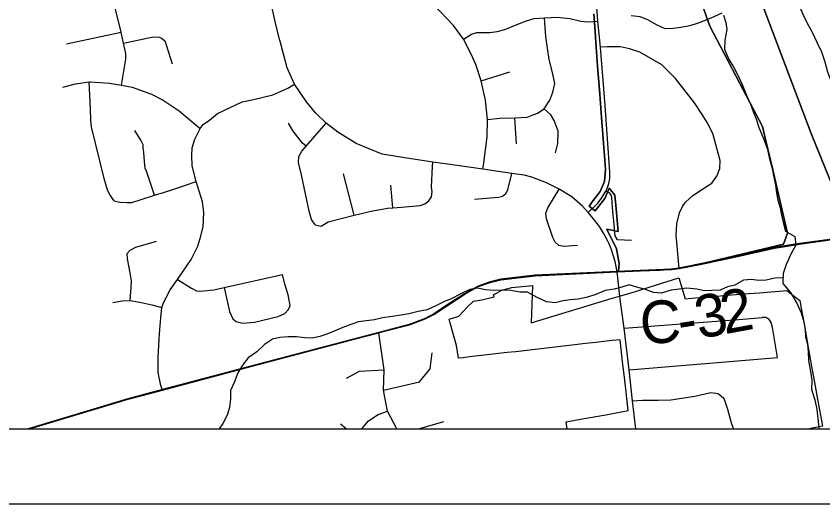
# Model space of a CAD drawing. Extents: x 0 to 34, y 0 to 22.
# Drawn here: x 13.284 to 14.359, y 3.284 to 3.934 of the extents above; entities that cross this region are included whole.
import ezdxf

# ---------------------------------------------------------------- set-up
doc = ezdxf.new("R2010")
doc.units = 0
for name, color, linetype in [('GM_X_City_Street', 7, 'Continuous'), ('GM_X_Corporation', 7, 'Continuous'), ('GM_X_County_Road', 7, 'Continuous'), ('GM_X_County_Road_Text', 7, 'Continuous'), ('GM_X_Major_River', 7, 'Continuous'), ('GM_X_Minor_River', 7, 'Continuous'), ('GM_X_Township_Road', 7, 'Continuous'), ('SH_Data', 7, 'Continuous')]:
    doc.layers.add(name, color=color, linetype=linetype)

msp = doc.modelspace()

# ---------------------------------------------------------------- linework, layer by layer
at = {"layer": 'GM_X_City_Street'}
for p, q in [((13.3512, 3.8973), (13.4237, 3.9129)), ((13.9039, 3.8481), (13.9422, 3.8599)), ((13.9508, 3.7642), (13.9488, 3.7987)), ((13.7344, 3.669), (13.7204, 3.7243)), ((13.786, 3.6789), (13.7836, 3.7088)), ((14.0819, 3.6463), (14.0801, 3.6657)), ((13.7237, 3.3841), (13.7163, 3.3904))]:
    msp.add_line(p, q, dxfattribs=at)
for points in [[(13.635, 3.9032), (13.629, 3.9271), (13.6186, 3.9755), (13.5999, 4.0534), (13.5519, 4.2807)], [(13.9123, 3.7967), (13.9094, 3.8222), (13.9039, 3.8481), (13.8968, 3.8698), (13.8907, 3.8836), (13.8802, 3.9037), (13.8671, 3.9217), (13.8411, 3.9489), (13.8248, 3.9626), (13.8, 3.986), (13.77, 4.011), (13.7495, 4.0206), (13.7309, 4.0238), (13.7079, 4.0206), (13.6893, 4.0135), (13.6778, 4.0065), (13.6669, 3.9937), (13.6571, 3.9868)], [(13.4241, 3.8422), (13.4288, 3.8688), (13.4301, 3.8768), (13.43, 3.8844), (13.4271, 3.8981), (13.4263, 3.9025), (13.4237, 3.9129), (13.4146, 3.9508), (13.4111, 3.9655), (13.4063, 3.9854), (13.4016, 4.0049)], [(13.8802, 3.9037), (13.8911, 3.9101), (13.8981, 3.9124), (13.907, 3.9127), (13.9154, 3.9127), (13.9253, 3.914), (13.9352, 3.9165), (13.955, 3.9245), (13.9643, 3.9281), (13.9746, 3.931), (13.9884, 3.9322), (13.9973, 3.9326)], [(13.9123, 3.7967), (13.9288, 3.7983), (13.9488, 3.7987), (13.9653, 3.7995), (13.9718, 3.8022), (13.9788, 3.805), (13.9878, 3.8108), (13.9955, 3.8221), (13.9994, 3.833), (14.0019, 3.8445), (13.9991, 3.8592), (13.9945, 3.8766), (13.9898, 3.9067), (13.9884, 3.9322)], [(13.9973, 3.9326), (14.0053, 3.9329), (14.0222, 3.9313), (14.0369, 3.9278), (14.0465, 3.9268), (14.0594, 3.9274)], [(13.4271, 3.8981), (13.4664, 3.9065), (13.474, 3.9064), (13.4772, 3.9054), (13.4821, 3.9016), (13.484, 3.8959), (13.4917, 3.8708)], [(14.0465, 3.6724), (14.0391, 3.6811), (14.0245, 3.6936), (14.0079, 3.7036), (13.991, 3.7122), (13.9713, 3.7197), (13.9613, 3.7222), (13.9447, 3.7247), (13.9061, 3.7305), (13.8654, 3.7362), (13.8394, 3.7398), (13.8019, 3.7452), (13.772, 3.7503), (13.7372, 3.7645), (13.7129, 3.7795), (13.6972, 3.7917), (13.6831, 3.8052), (13.671, 3.82), (13.655, 3.8436), (13.645, 3.8656), (13.6353, 3.9021), (13.635, 3.9032)], [(14.1677, 3.5979), (14.1637, 3.6421), (14.1645, 3.6575), (14.1681, 3.672), (14.1724, 3.6807), (14.1764, 3.6863), (14.1861, 3.6954), (14.2016, 3.7053), (14.2112, 3.7118), (14.2182, 3.721), (14.222, 3.7311), (14.2226, 3.7418), (14.2125, 3.778), (14.2051, 3.7924), (14.1995, 3.802), (14.1882, 3.8187), (14.163, 3.8512), (14.1447, 3.8692), (14.1154, 3.8864), (14.1016, 3.8909), (14.0894, 3.8932), (14.0717, 3.8936), (14.0627, 3.8929)], [(13.346, 3.8397), (13.363, 3.844), (13.3811, 3.8466), (13.3824, 3.8468), (13.4083, 3.8451), (13.4241, 3.8422), (13.4386, 3.8396), (13.4642, 3.8302), (13.4799, 3.8222), (13.5012, 3.8082), (13.5294, 3.7847)], [(13.4146, 3.6881), (13.4091, 3.6957), (13.4058, 3.7023), (13.4012, 3.718), (13.3843, 3.7867), (13.3835, 3.7953), (13.3832, 3.8106), (13.3811, 3.8466)], [(13.4792, 3.4358), (13.4769, 3.4417), (13.473, 3.4593), (13.473, 3.4794), (13.4751, 3.5113), (13.4766, 3.5323), (13.4783, 3.5458), (13.4801, 3.5521), (13.489, 3.5693), (13.499, 3.5834), (13.5174, 3.6098), (13.5259, 3.6275), (13.5297, 3.6398), (13.5331, 3.6536), (13.5339, 3.6725), (13.5322, 3.6869), (13.524, 3.7138), (13.5186, 3.7347), (13.518, 3.7487), (13.5187, 3.7588), (13.522, 3.7701), (13.5294, 3.7847), (13.5334, 3.7899), (13.5416, 3.7956), (13.5523, 3.8046), (13.5853, 3.8202), (13.6005, 3.823), (13.6259, 3.8294), (13.6462, 3.8382), (13.655, 3.8436)], [(14.0031, 3.7521), (14.0062, 3.7644), (14.0064, 3.7811), (14.0013, 3.7952), (13.9966, 3.8026), (13.9878, 3.8108)], [(13.9061, 3.7305), (13.9072, 3.7389), (13.9119, 3.7736), (13.9123, 3.7967)], [(13.6704, 3.761), (13.6654, 3.765), (13.6531, 3.7808), (13.6469, 3.7917)], [(13.6827, 3.656), (13.6777, 3.6633), (13.6744, 3.6744), (13.6642, 3.7227), (13.6605, 3.7392), (13.6609, 3.7471), (13.6646, 3.7541), (13.6704, 3.761), (13.6972, 3.7917)], [(13.4684, 3.6955), (13.4577, 3.7276), (13.4559, 3.7318), (13.4551, 3.7403), (13.454, 3.7529), (13.4534, 3.7583), (13.4531, 3.7627), (13.4503, 3.7691), (13.442, 3.7819)], [(13.6827, 3.656), (13.6905, 3.6542), (13.6998, 3.66), (13.7344, 3.669), (13.7571, 3.6745), (13.7789, 3.6782), (13.786, 3.6789), (13.7977, 3.6797), (13.8226, 3.6819), (13.8287, 3.684), (13.8339, 3.6879), (13.8375, 3.6934), (13.8384, 3.6999), (13.8378, 3.7063), (13.8389, 3.7339), (13.8394, 3.7398)], [(13.8949, 3.6904), (13.9268, 3.6929), (13.9323, 3.6943), (13.9367, 3.6979), (13.9393, 3.7029), (13.9447, 3.7247)], [(13.4146, 3.6881), (13.4222, 3.6863), (13.4314, 3.6858), (13.4381, 3.686), (13.4491, 3.6893), (13.4684, 3.6955), (13.4801, 3.6993), (13.4952, 3.704), (13.524, 3.7138)], [(14.0324, 3.6285), (14.014, 3.627), (14.0074, 3.6287), (14.0023, 3.6332), (13.9995, 3.6394), (13.9907, 3.6642), (13.99, 3.6718), (13.9925, 3.6789), (14.0079, 3.7036)], [(14.0801, 3.6657), (14.0798, 3.6686), (14.0783, 3.6854), (14.078, 3.693), (14.0771, 3.6958), (14.0753, 3.6981), (14.07, 3.7011)], [(14.0739, 3.6316), (14.0732, 3.6335), (14.0671, 3.645), (14.0617, 3.6539), (14.0537, 3.6643), (14.0465, 3.6724)], [(14.1044, 3.635), (14.0855, 3.6363), (14.0824, 3.6415), (14.0819, 3.6463)], [(13.436, 3.5552), (13.4372, 3.5724), (13.4375, 3.5814), (13.4357, 3.592), (13.4321, 3.6106), (13.4318, 3.618), (13.4357, 3.6224), (13.4434, 3.6263), (13.4709, 3.6345)], [(14.0852, 3.5936), (14.0825, 3.6073), (14.0769, 3.6241), (14.0739, 3.6316)], [(13.499, 3.5834), (13.5177, 3.5718), (13.5245, 3.5683), (13.5289, 3.5675), (13.534, 3.568), (13.5473, 3.5694), (13.5611, 3.5725), (13.639, 3.5899)], [(13.5611, 3.5725), (13.5681, 3.5407), (13.5727, 3.5308), (13.5774, 3.5273), (13.5859, 3.5251), (13.6018, 3.5262), (13.6334, 3.5341), (13.642, 3.5381), (13.6471, 3.5432), (13.6493, 3.5485), (13.6463, 3.5628), (13.6419, 3.5771), (13.639, 3.5899)], [(13.4129, 3.5524), (13.4254, 3.5546), (13.436, 3.5552), (13.4486, 3.5528), (13.4647, 3.5496), (13.4783, 3.5458)], [(13.7916, 3.3841), (13.7789, 3.4077), (13.7737, 3.4355), (13.7743, 3.4629), (13.7674, 3.5122)], [(13.7737, 3.4355), (13.8214, 3.4467), (13.836, 3.4643), (13.8385, 3.4853)], [(13.7244, 3.4518), (13.7418, 3.4609), (13.7743, 3.4629)], [(13.7448, 3.3841), (13.7537, 3.3949), (13.7663, 3.4031), (13.7789, 3.4077)], [(13.8202, 3.3841), (13.8219, 3.3848), (13.854, 3.3938)]]:
    msp.add_lwpolyline(points, dxfattribs=at)
at = {"layer": 'GM_X_Corporation'}
for points in [[(12.7646, 8.6719), (12.7646, 3.3841), (19.5646, 3.3841), (19.5646, 8.318)], [(12.7646, 8.6719), (12.7646, 3.3841), (13.2998, 3.3841), (13.4327, 3.4241), (13.4789, 3.4364), (13.6099, 3.4712), (13.7672, 3.5127), (13.8079, 3.5231), (13.829, 3.5313), (13.8415, 3.5378), (13.8572, 3.5484), (13.8817, 3.5643), (13.8998, 3.5742), (13.9157, 3.5799), (13.9299, 3.5835), (13.9754, 3.5888), (14.085, 3.5941), (14.1571, 3.5969), (14.1675, 3.5985), (14.2018, 3.6051), (14.2415, 3.6134), (14.2946, 3.6257), (14.328, 3.631), (14.375, 3.6376)], [(14.4, 3.6389), (14.3439, 3.7779), (14.2585, 4.0037), (14.2228, 4.1239), (14.1834, 4.3256), (14.1653, 4.4698)], [(14.1653, 4.4698), (14.1834, 4.3256), (14.2228, 4.1239), (14.2585, 4.0037), (14.3439, 3.7779), (14.4, 3.6389)], [(14.0541, 3.9374), (14.0552, 3.9202), (14.0572, 3.893), (14.0595, 3.8618), (14.0603, 3.852), (14.0619, 3.8304), (14.0643, 3.799), (14.0665, 3.7706), (14.0687, 3.7422), (14.0697, 3.7297), (14.0683, 3.7145), (14.067, 3.7108), (14.0626, 3.7004), (14.0533, 3.6884), (14.048, 3.681), (14.0556, 3.6748), (14.0686, 3.691), (14.0745, 3.7049), (14.0818, 3.6958), (14.0836, 3.6776), (14.0866, 3.6474), (14.0715, 3.6501), (14.0843, 3.6241), (14.0877, 3.6045), (14.0869, 3.5941), (14.1423, 3.5958), (14.1573, 3.5969), (14.1675, 3.5985), (14.2018, 3.6051), (14.3069, 3.6302), (14.3122, 3.645), (14.3015, 3.6909), (14.2925, 3.7296), (14.2835, 3.7682), (14.279, 3.7873), (14.2701, 3.8041), (14.2486, 3.8445), (14.2276, 3.8847), (14.2086, 3.9211), (14.1912, 3.9702)], [(14.1912, 3.9702), (14.2086, 3.9211), (14.2276, 3.8847), (14.2486, 3.8445), (14.2701, 3.8041), (14.279, 3.7873), (14.2835, 3.7682), (14.2925, 3.7296), (14.3015, 3.6909), (14.3122, 3.645), (14.3069, 3.6302), (14.2026, 3.6053), (14.1675, 3.5985), (14.1573, 3.5969), (14.1423, 3.5958), (14.0869, 3.5941), (14.0877, 3.6047), (14.0843, 3.6241), (14.0715, 3.6501), (14.0866, 3.6474), (14.0836, 3.6776), (14.0818, 3.6958), (14.0745, 3.7049), (14.0686, 3.691), (14.0556, 3.6748), (14.048, 3.681), (14.0533, 3.6884), (14.0626, 3.7004), (14.067, 3.7108), (14.0683, 3.7145), (14.0697, 3.7297), (14.0687, 3.7422), (14.0665, 3.7706), (14.0643, 3.799), (14.0619, 3.8304), (14.0595, 3.8618), (14.0572, 3.893), (14.0552, 3.9202), (14.0541, 3.9374)], [(14.375, 3.6376), (14.328, 3.631), (14.2946, 3.6257), (14.2415, 3.6134), (14.2018, 3.6051), (14.1675, 3.5985), (14.1571, 3.5969), (14.085, 3.5941), (13.9754, 3.5888), (13.9299, 3.5835), (13.9157, 3.5799), (13.8998, 3.5742), (13.8817, 3.5643), (13.8572, 3.5484), (13.8415, 3.5378), (13.829, 3.5313), (13.8079, 3.5231), (13.7672, 3.5127), (13.6099, 3.4712), (13.4789, 3.4364), (13.4327, 3.4241), (13.2998, 3.3841), (14.4192, 3.3841)], [(13.0687, 3.3841), (14.0184, 3.3841), (14.0171, 3.3935), (14.0413, 3.3979), (14.0698, 3.403), (14.1, 3.4085), (14.0995, 3.4127), (14.0962, 3.4408), (14.0947, 3.4531), (14.0927, 3.47), (14.0889, 3.5026), (14.0784, 3.5019), (14.0675, 3.5006), (14.0567, 3.4994), (14.0427, 3.4978), (14.0287, 3.4962), (14.0174, 3.4949), (14.0061, 3.4936), (13.9948, 3.4923), (13.9835, 3.491), (13.9722, 3.4896), (13.961, 3.4883), (13.9497, 3.487), (13.9384, 3.4857), (13.9271, 3.4844), (13.9158, 3.4831), (13.9004, 3.4814), (13.8883, 3.48), (13.8796, 3.479), (13.8735, 3.4782), (13.8708, 3.4953), (13.8622, 3.5268), (13.8612, 3.5305), (13.874, 3.5343), (13.8857, 3.547), (13.8936, 3.5543), (13.9046, 3.556), (13.921, 3.5599), (13.9203, 3.5629), (13.9312, 3.569), (13.9449, 3.5724), (13.9722, 3.575), (13.9706, 3.5256), (14.0772, 3.5581), (14.1036, 3.5656), (14.1363, 3.5758), (14.1673, 3.5855), (14.1756, 3.5575), (14.1897, 3.5586), (14.2039, 3.5598), (14.218, 3.5609), (14.2321, 3.5622), (14.2606, 3.5644), (14.2747, 3.5654), (14.3113, 3.5684), (14.3285, 3.5552), (14.3304, 3.5448), (14.3338, 3.5262), (14.336, 3.5136), (14.3403, 3.4898), (14.3444, 3.4674), (14.3465, 3.4556), (14.3487, 3.4437), (14.3527, 3.4211), (14.3561, 3.4023), (14.3588, 3.3877), (14.3412, 3.3841), (14.5215, 3.3841)]]:
    msp.add_lwpolyline(points, dxfattribs=at)
at = {"layer": 'GM_X_County_Road'}
msp.add_line((14.0887, 3.561), (14.0852, 3.5936), dxfattribs=at)
for points in [[(14.07, 3.7011), (14.0716, 3.7047), (14.0739, 3.7113), (14.0752, 3.7177), (14.0752, 3.7265), (14.0693, 3.8153), (14.0627, 3.8929), (14.0594, 3.9274), (14.052, 4.0359), (14.049, 4.0744), (14.0366, 4.2397), (14.0264, 4.3631), (14.0059, 4.4877), (13.9877, 4.5872), (13.9741, 4.6416), (13.9708, 4.6584), (13.9579, 4.7101), (13.9565, 4.7165), (13.9561, 4.7239), (13.9561, 4.7298), (13.9561, 4.7351)], [(14.0465, 3.6724), (14.0593, 3.6852), (14.0644, 3.6915), (14.07, 3.7011)], [(14.0739, 3.6316), (14.0732, 3.6335), (14.0671, 3.645), (14.0617, 3.6539), (14.0537, 3.6643), (14.0465, 3.6724)], [(14.309, 3.6274), (14.3282, 3.6304), (14.3752, 3.637), (14.4003, 3.6384)], [(14.0852, 3.5936), (14.0825, 3.6073), (14.0769, 3.6241), (14.0739, 3.6316)], [(14.1979, 3.6038), (14.202, 3.6046), (14.2417, 3.6129), (14.2948, 3.6251), (14.309, 3.6274)], [(14.0852, 3.5936), (14.1574, 3.5964), (14.1677, 3.5979), (14.1979, 3.6038)], [(13.7769, 3.5146), (13.8082, 3.5226), (13.8292, 3.5307), (13.8417, 3.5372), (13.8574, 3.5478), (13.8819, 3.5637), (13.9, 3.5737), (13.9159, 3.5794), (13.9301, 3.5829), (13.9756, 3.5882), (14.0852, 3.5936)], [(14.1101, 3.3841), (14.1057, 3.4215), (14.1009, 3.4627), (14.0946, 3.5183), (14.0895, 3.5534), (14.0887, 3.561)], [(13.3018, 3.3841), (13.433, 3.4236), (13.4792, 3.4358), (13.6101, 3.4707), (13.7482, 3.5071)], [(13.7482, 3.5071), (13.7674, 3.5122), (13.7769, 3.5146)]]:
    msp.add_lwpolyline(points, dxfattribs=at)
at = {"layer": 'GM_X_Major_River'}
msp.add_line((14.354, 3.3857), (14.3543, 3.3841), dxfattribs=at)
for points in [[(14.375, 3.8387), (14.3695, 3.8502), (14.3659, 3.8598), (14.3624, 3.8731), (14.3581, 3.8861), (14.3519, 3.8991), (14.3457, 3.9126), (14.3388, 3.9245), (14.3333, 3.9367), (14.3268, 3.9513), (14.3207, 3.9658), (14.3156, 3.9785), (14.3113, 3.9911), (14.3085, 4.0006), (14.3046, 4.0128), (14.3018, 4.0258), (14.299, 4.0365), (14.2951, 4.0495), (14.2908, 4.0629)], [(14.2268, 3.9358), (14.23, 3.9258), (14.2313, 3.9163), (14.2288, 3.9023), (14.2282, 3.8905), (14.2336, 3.8772), (14.2402, 3.8668), (14.2457, 3.8564), (14.2518, 3.843), (14.2573, 3.83), (14.2627, 3.817), (14.2663, 3.8074), (14.271, 3.7959), (14.2742, 3.786), (14.2803, 3.7714), (14.285, 3.7581), (14.2881, 3.7439), (14.2917, 3.731), (14.2941, 3.7195), (14.2961, 3.7089), (14.2974, 3.6986), (14.2995, 3.689), (14.3024, 3.6787), (14.3041, 3.6692), (14.3065, 3.6597), (14.3097, 3.6478), (14.322, 3.6404), (14.3233, 3.629), (14.317, 3.6177), (14.3103, 3.6034), (14.3063, 3.5913), (14.306, 3.5777), (14.3164, 3.5657), (14.3248, 3.5515), (14.3302, 3.5388), (14.3338, 3.5266), (14.3358, 3.5167), (14.3364, 3.5068), (14.3388, 3.4969), (14.3398, 3.4874), (14.3403, 3.4752), (14.3427, 3.4607), (14.3447, 3.4489), (14.3444, 3.4364), (14.3487, 3.423), (14.3515, 3.41), (14.354, 3.3857)]]:
    msp.add_lwpolyline(points, dxfattribs=at)
at = {"layer": 'GM_X_Minor_River'}
for points in [[(14.2246, 3.9381), (14.2142, 3.9336), (14.2047, 3.9292), (14.1917, 3.9244), (14.1818, 3.9212), (14.17, 3.9191), (14.1598, 3.9177), (14.1492, 3.9175), (14.1375, 3.9226), (14.1258, 3.9292), (14.116, 3.9332), (14.1039, 3.9345)], [(14.3061, 3.5856), (14.2955, 3.585), (14.2837, 3.5825), (14.2742, 3.5819), (14.2644, 3.5832), (14.2534, 3.5822), (14.2419, 3.5755), (14.2324, 3.5734), (14.2225, 3.569), (14.2111, 3.5684), (14.2016, 3.5682), (14.1914, 3.5702), (14.1782, 3.5716), (14.1679, 3.5702), (14.1573, 3.5688), (14.1444, 3.5652), (14.1334, 3.5661), (14.1228, 3.5697), (14.1115, 3.5729), (14.1013, 3.5761), (14.0914, 3.5732), (14.0811, 3.5703), (14.069, 3.5686), (14.0568, 3.5631), (14.0454, 3.5598), (14.0332, 3.557), (14.0226, 3.556), (14.0131, 3.555), (14.0024, 3.5521), (13.9907, 3.5534), (13.9786, 3.5593), (13.9655, 3.5663), (13.9556, 3.5665), (13.9428, 3.5686), (13.9321, 3.5691), (13.92, 3.5685), (13.9098, 3.5694), (13.8988, 3.5715), (13.8886, 3.5701), (13.8767, 3.5639), (13.8638, 3.5576), (13.8542, 3.5535), (13.8443, 3.5484), (13.8317, 3.5429), (13.8199, 3.5407), (13.8074, 3.5375), (13.7971, 3.5358), (13.785, 3.5337), (13.7721, 3.5323), (13.7614, 3.5294), (13.7504, 3.5281), (13.7402, 3.5267), (13.7302, 3.5231), (13.7196, 3.5194), (13.7078, 3.5143), (13.6982, 3.5102), (13.6887, 3.5073), (13.6784, 3.5048), (13.6686, 3.5054), (13.6576, 3.5067), (13.6466, 3.5068), (13.6352, 3.5058), (13.6257, 3.5037), (13.615, 3.4966), (13.6047, 3.4869), (13.5932, 3.4787), (13.5858, 3.4689), (13.5793, 3.4588), (13.5745, 3.4459), (13.5695, 3.4354), (13.5697, 3.424), (13.5684, 3.4126), (13.5652, 3.4024), (13.5594, 3.3914), (13.5546, 3.3841)]]:
    msp.add_lwpolyline(points, dxfattribs=at)
at = {"layer": 'GM_X_Township_Road'}
msp.add_line((14.1009, 3.4627), (14.299, 3.4792), dxfattribs=at)
for points in [[(14.0946, 3.5183), (14.2526, 3.5304), (14.2786, 3.5326)], [(14.299, 3.4792), (14.2922, 3.5194), (14.2905, 3.5257), (14.2877, 3.5301), (14.2834, 3.5324), (14.2786, 3.5326)], [(14.1057, 3.4215), (14.1187, 3.4223), (14.1396, 3.4223), (14.1565, 3.4229), (14.1887, 3.4275), (14.2098, 3.4324), (14.2197, 3.4312), (14.2274, 3.4249), (14.2323, 3.4105), (14.2377, 3.391), (14.2401, 3.3841)]]:
    msp.add_lwpolyline(points, dxfattribs=at)
at = {"layer": 'SH_Data'}
for p, q in [((12.7646, 3.3841), (19.5646, 3.3841)), ((12.6646, 3.2841), (19.6646, 3.2841))]:
    msp.add_line(p, q, dxfattribs=at)

# ---------------------------------------------------------------- texts
at = {"layer": 'GM_X_County_Road_Text'}
for s, rotation, p in [('2', 10.4479, (14.2283, 3.5102)), ('3', 10.4763, (14.1942, 3.5039)), ('C', 2.6576, (14.1166, 3.4972)), ('-', 8.8973, (14.1696, 3.5))]:
    msp.add_text(s, height=0.0568, rotation=rotation, dxfattribs=at).set_placement(p)

doc.saveas('drawing.dxf')
